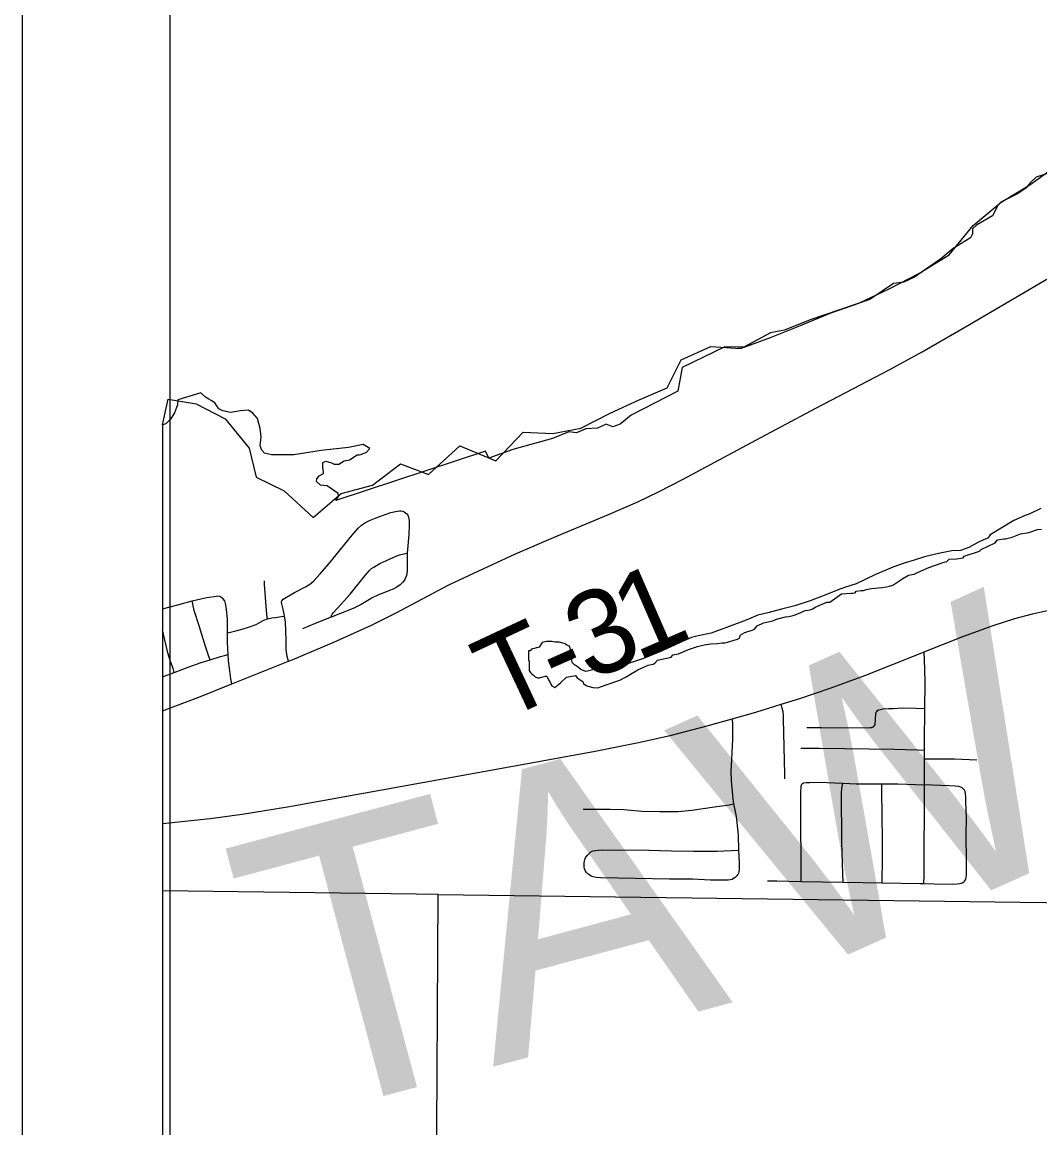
# Model space of a CAD drawing. Extents: x 63.4 to 97.4, y 0.4 to 22.4.
# Drawn here: x 65.412 to 66.101, y 16.424 to 17.173 of the extents above; entities that cross this region are included whole.
import ezdxf

# ---------------------------------------------------------------- set-up
doc = ezdxf.new("R2010")
doc.units = 0
for name, color, linetype in [('GM_X_Corporation_Text', 7, 'Continuous'), ('GM_X_County_Road', 7, 'Continuous'), ('GM_X_County_Text', 7, 'Continuous'), ('GM_X_Major_Lake', 7, 'Continuous'), ('GM_X_Minor_River', 7, 'Continuous'), ('GM_X_Section', 7, 'Continuous'), ('GM_X_State_Route', 7, 'Continuous'), ('GM_X_Township_Road', 7, 'Continuous'), ('GM_X_Township_Road_Text', 7, 'Continuous'), ('SH_Cut_Line', 7, 'Continuous'), ('SH_Data', 7, 'Continuous')]:
    doc.layers.add(name, color=color, linetype=linetype)

msp = doc.modelspace()

# ---------------------------------------------------------------- linework, layer by layer
at = {"layer": 'GM_X_Corporation_Text'}
msp.add_lwpolyline([(65.50725, 16.58499), (65.50725, 15.58676), (65.68816, 15.5852), (65.69377, 16.5825), (65.67899, 16.58257)], close=True, dxfattribs=at)
at = {"layer": 'GM_X_County_Road'}
msp.add_lwpolyline([(66.11345, 17.07252), (66.09849, 17.06781), (66.09476, 17.06423), (66.09167, 17.06049), (66.08598, 17.05659), (66.0746, 17.05107), (66.07265, 17.04863), (66.06892, 17.04164), (66.05819, 17.03546), (66.05542, 17.03286), (66.05542, 17.02945), (66.05412, 17.02685), (66.04242, 17.01969), (66.03413, 17.01254), (66.01614, 17.00026), (66.0091, 16.99694), (66.00211, 16.99596), (65.98608, 16.98501), (65.94571, 16.97126), (65.92815, 16.96427), (65.91873, 16.96248), (65.90068, 16.95273), (65.89646, 16.95273), (65.88784, 16.95305), (65.85907, 16.93908), (65.85599, 16.92315), (65.82445, 16.90689), (65.81697, 16.90071), (65.8121, 16.89893), (65.80754, 16.90071), (65.80169, 16.89811), (65.79389, 16.89763), (65.78755, 16.89486), (65.78235, 16.89551), (65.7713, 16.89096), (65.74431, 16.88348), (65.72823, 16.8778), (65.72595, 16.88251), (65.62468, 16.84903), (65.62647, 16.85179), (65.62615, 16.8539), (65.61883, 16.85894), (65.61428, 16.85943), (65.61152, 16.86187), (65.61168, 16.86382), (65.6133, 16.86577), (65.61623, 16.86723), (65.61623, 16.8687), (65.61575, 16.87113), (65.61591, 16.87487), (65.61786, 16.87569), (65.62159, 16.87454), (65.62338, 16.87357), (65.62663, 16.87357), (65.63021, 16.87585), (65.63395, 16.87649), (65.63915, 16.87991), (65.64061, 16.87991), (65.64517, 16.88153), (65.64763, 16.88434), (65.64305, 16.88706), (65.63324, 16.88498), (65.61461, 16.88284), (65.59608, 16.88007), (65.58112, 16.87991), (65.57641, 16.88105), (65.57462, 16.88316), (65.57332, 16.88609), (65.57413, 16.8921), (65.57348, 16.89779), (65.57153, 16.90462), (65.56845, 16.90819), (65.56552, 16.91014), (65.55999, 16.90982), (65.55333, 16.90852), (65.54813, 16.90966), (65.54552, 16.91112), (65.54276, 16.91518), (65.54032, 16.91681), (65.5387, 16.91762), (65.53642, 16.91892), (65.53333, 16.92201), (65.51773, 16.91729), (65.51757, 16.91372), (65.51546, 16.90835), (65.51269, 16.90413), (65.50976, 16.90121), (65.50725, 16.90012), (65.50725, 14.70733)], dxfattribs=at)
at = {"layer": 'GM_X_Major_Lake'}
msp.add_lwpolyline([(65.50725, 16.90027), (65.51106, 16.91762), (65.53002, 16.91459), (65.54973, 16.90433), (65.56604, 16.88458), (65.57059, 16.86483), (65.58956, 16.85572), (65.60927, 16.83748), (65.62823, 16.85382), (65.64947, 16.85952), (65.66842, 16.87396), (65.68738, 16.86675), (65.70862, 16.88612), (65.73289, 16.87587), (65.75146, 16.89524), (65.77156, 16.89449), (65.79052, 16.89791), (65.81024, 16.90817), (65.82995, 16.91729), (65.84891, 16.92527), (65.85839, 16.94426), (65.87849, 16.95338), (65.89858, 16.95186), (65.91868, 16.95946), (65.93916, 16.96744), (65.95925, 16.9758), (65.97859, 16.98264), (65.99944, 16.99252), (66.01916, 17.00278), (66.03963, 17.01532), (66.05594, 17.03507), (66.07489, 17.05103), (66.09423, 17.06281), (66.11926, 17.08066)], dxfattribs=at)
at = {"layer": 'GM_X_Minor_River'}
for points in [[(66.10181, 16.84376), (66.09419, 16.84002), (66.09114, 16.83891), (66.08352, 16.83555), (66.06749, 16.82579), (66.06595, 16.82353), (66.06291, 16.82241), (66.0591, 16.82054), (66.05299, 16.81717), (66.04728, 16.81531), (66.04158, 16.81498), (66.03245, 16.81314), (66.02294, 16.81094), (66.01609, 16.80871), (66.01, 16.80686), (66.00162, 16.80388), (65.98942, 16.79866), (65.97684, 16.79268), (65.96885, 16.79008), (65.96466, 16.78859), (65.95628, 16.78523), (65.94561, 16.78114), (65.93533, 16.7778), (65.9262, 16.77559), (65.91706, 16.773), (65.91022, 16.77153), (65.90221, 16.76817), (65.89079, 16.7637), (65.8786, 16.75923), (65.86985, 16.7574), (65.86528, 16.7563), (65.85766, 16.75293), (65.84546, 16.74733), (65.83289, 16.74211), (65.82261, 16.73877), (65.81615, 16.73768), (65.81043, 16.73582), (65.80549, 16.73472), (65.80397, 16.73511), (65.79865, 16.73439), (65.79484, 16.73366), (65.7937, 16.73329), (65.79219, 16.73406), (65.79067, 16.73445), (65.78879, 16.73598), (65.78614, 16.7379), (65.78463, 16.73943), (65.78427, 16.74133), (65.78428, 16.74285), (65.78392, 16.74513), (65.78393, 16.74741), (65.78319, 16.74894), (65.78282, 16.75046), (65.78093, 16.75123), (65.77979, 16.752), (65.776, 16.75316), (65.77296, 16.75319), (65.77069, 16.75359), (65.76727, 16.75361), (65.76423, 16.75287), (65.76231, 16.74985), (65.75698, 16.74837), (65.75621, 16.74724), (65.75507, 16.74725), (65.75505, 16.74421), (65.75502, 16.74117), (65.75539, 16.74003), (65.75535, 16.73395), (65.7561, 16.73281), (65.75723, 16.73166), (65.75836, 16.73089), (65.75949, 16.72975), (65.76101, 16.72898), (65.76252, 16.72896), (65.76633, 16.73007), (65.76747, 16.73007), (65.76859, 16.72778), (65.76934, 16.72626), (65.77009, 16.72473), (65.77084, 16.72359), (65.77273, 16.72243), (65.77693, 16.72582), (65.78076, 16.72959), (65.78685, 16.73068), (65.78798, 16.72915), (65.78986, 16.72762), (65.79175, 16.72647), (65.79213, 16.72532), (65.79363, 16.72417), (65.79515, 16.7234), (65.79856, 16.72262), (65.80198, 16.72221), (65.80693, 16.72407)], [(65.80693, 16.72407), (65.81683, 16.72742), (65.82102, 16.72967), (65.82407, 16.73154), (65.82904, 16.73454), (65.8359, 16.73753), (65.83932, 16.73826), (65.84046, 16.73901), (65.84238, 16.7409), (65.85151, 16.74311), (65.85266, 16.74462), (65.85646, 16.74535), (65.86332, 16.74834), (65.86941, 16.75019), (65.87398, 16.75129), (65.87816, 16.75202), (65.88273, 16.75237), (65.88615, 16.75272), (65.88805, 16.75271), (65.88957, 16.75308), (65.89642, 16.7553), (65.89795, 16.75605), (65.89834, 16.75795), (65.90139, 16.75982), (65.90634, 16.7613), (65.90787, 16.76205), (65.90978, 16.76432), (65.91398, 16.76618), (65.92044, 16.76765), (65.92273, 16.76878), (65.92882, 16.77025), (65.9311, 16.77061), (65.93414, 16.77135), (65.93719, 16.77247), (65.94215, 16.77471), (65.94557, 16.77506), (65.94747, 16.77581), (65.949, 16.77693), (65.957, 16.78029), (65.9589, 16.78028), (65.96692, 16.78591), (65.97338, 16.78625), (65.97452, 16.78624), (65.97604, 16.78661), (65.97681, 16.78774), (65.98023, 16.78809), (65.98175, 16.78808), (65.98365, 16.78883), (65.98708, 16.78956), (65.9943, 16.79026), (65.99734, 16.79062), (65.99924, 16.79099), (66.00152, 16.79173), (66.0084, 16.79624), (66.01221, 16.79849), (66.01601, 16.79922), (66.0183, 16.80034), (66.02592, 16.8037), (66.0343, 16.80667), (66.03544, 16.80705), (66.03811, 16.80779), (66.03964, 16.80929), (66.04458, 16.80964), (66.04914, 16.81036), (66.04991, 16.8115), (66.06019, 16.81484), (66.06134, 16.81597), (66.07087, 16.82045), (66.0724, 16.82234), (66.07659, 16.82307), (66.07773, 16.82306), (66.08229, 16.82416), (66.08801, 16.8264), (66.09371, 16.8275), (66.09942, 16.82935), (66.10209, 16.82971)]]:
    msp.add_lwpolyline(points, dxfattribs=at)
at = {"layer": 'GM_X_Section'}
msp.add_lwpolyline([(66.68776, 16.56928), (66.716, 16.56874), (66.70719, 15.57748), (66.70364, 15.57723), (65.68816, 15.5852), (65.69377, 16.5825)], close=True, dxfattribs=at)
at = {"layer": 'GM_X_State_Route'}
msp.add_lwpolyline([(65.50725, 16.63058), (65.53967, 16.63392), (65.56126, 16.63686), (65.59197, 16.64181), (65.68072, 16.65771), (65.7419, 16.66891), (65.80002, 16.67946), (65.83054, 16.68546), (65.85179, 16.69028), (65.8759, 16.69649), (65.89273, 16.7013), (65.9088, 16.70591), (65.92589, 16.71117), (65.93854, 16.71506), (65.95917, 16.72206), (65.98252, 16.73068), (66.02012, 16.74555), (66.02288, 16.74664), (66.04902, 16.75696), (66.06945, 16.76436), (66.08421, 16.76911), (66.09617, 16.77234), (66.1113, 16.77566)], dxfattribs=at)
at = {"layer": 'GM_X_Township_Road'}
for p, q in [((65.55432, 16.72498), (65.59259, 16.74035)), ((65.50725, 16.72971), (65.51532, 16.73273)), ((66.02296, 16.67425), (66.02297, 16.68014)), ((65.93953, 16.59131), (65.96786, 16.59078)), ((65.96786, 16.59078), (65.99438, 16.59031))]:
    msp.add_line(p, q, dxfattribs=at)
for points in [[(65.59259, 16.74035), (65.59502, 16.74133), (65.62337, 16.75324), (65.64882, 16.76471), (65.66548, 16.77301), (65.70117, 16.79192), (65.71801, 16.79998), (65.74624, 16.81297), (65.77193, 16.82404), (65.8092, 16.83953), (65.8291, 16.84824), (65.84308, 16.85488), (65.85959, 16.86344), (65.90882, 16.88996), (65.94996, 16.91189), (65.99959, 16.93762), (66.02131, 16.94965), (66.05337, 16.96811), (66.10431, 16.99791), (66.18101, 17.04274)], [(65.58991, 16.77076), (65.58936, 16.77337), (65.58866, 16.77646), (65.58796, 16.77913), (65.58774, 16.77994), (65.58774, 16.78064), (65.58796, 16.78123), (65.58898, 16.78219), (65.59117, 16.78369), (65.59654, 16.7867), (65.60408, 16.79057), (65.60633, 16.79201), (65.60789, 16.7932), (65.60973, 16.79472), (65.61406, 16.79937), (65.61977, 16.80627), (65.63561, 16.82566), (65.63973, 16.83031), (65.64203, 16.8324), (65.64459, 16.83414), (65.64736, 16.83555), (65.65314, 16.8378), (65.66194, 16.84089), (65.66499, 16.84172), (65.66764, 16.84215), (65.66888, 16.84212), (65.66987, 16.84186), (65.67077, 16.84146), (65.67186, 16.84074), (65.67266, 16.84008), (65.67324, 16.83921), (65.67382, 16.83784), (65.67411, 16.8366), (65.67418, 16.83544), (65.67426, 16.83217), (65.67393, 16.82612), (65.67286, 16.81332)], [(65.62146, 16.77009), (65.62171, 16.77133), (65.62207, 16.77206), (65.62279, 16.77308), (65.62585, 16.77627), (65.63426, 16.78571), (65.64341, 16.79704), (65.6458, 16.79986), (65.64733, 16.80161), (65.64878, 16.80299), (65.65023, 16.804), (65.65205, 16.80516), (65.65437, 16.8064), (65.66584, 16.81163), (65.6678, 16.81228), (65.66947, 16.81264), (65.67286, 16.81332)], [(65.67286, 16.81332), (65.67283, 16.80754), (65.67293, 16.80444), (65.67285, 16.80132), (65.67237, 16.79842), (65.67178, 16.79677), (65.67107, 16.79508), (65.66983, 16.79348), (65.66816, 16.79188), (65.66597, 16.79037), (65.66337, 16.78905), (65.66098, 16.78811), (65.65819, 16.787), (65.65537, 16.78588), (65.6527, 16.78476), (65.64972, 16.78332), (65.64186, 16.77859), (65.6363, 16.77599), (65.62774, 16.77254), (65.62146, 16.77009)], [(65.57827, 16.76895), (65.57803, 16.7719), (65.57756, 16.77757), (65.57645, 16.79217), (65.57637, 16.79477)], [(65.50725, 16.77581), (65.51778, 16.77856), (65.52749, 16.78106)], [(65.52749, 16.78106), (65.53331, 16.78255), (65.53725, 16.78334), (65.54393, 16.78422)], [(65.53949, 16.74127), (65.5387, 16.74356), (65.53665, 16.74948), (65.53214, 16.76417), (65.52885, 16.77467), (65.52793, 16.77901), (65.52749, 16.78106)], [(65.55132, 16.75962), (65.55119, 16.76893), (65.55059, 16.7752), (65.55012, 16.77849), (65.54946, 16.78124), (65.54815, 16.78282), (65.54605, 16.784), (65.54393, 16.78422)], [(65.57827, 16.76895), (65.58137, 16.76957), (65.58387, 16.76996), (65.58781, 16.77048), (65.58991, 16.77076)], [(65.59259, 16.74035), (65.59171, 16.74351), (65.59106, 16.74825), (65.59106, 16.75447), (65.59048, 16.76697), (65.58991, 16.77076)], [(65.55132, 16.75962), (65.5542, 16.76024), (65.55787, 16.76103), (65.56129, 16.76195), (65.56562, 16.76339), (65.57061, 16.76523), (65.57397, 16.76686), (65.57599, 16.76799), (65.57827, 16.76895)], [(65.62146, 16.77009), (65.61055, 16.76583), (65.60213, 16.76231)], [(65.51532, 16.73273), (65.51442, 16.73528), (65.51271, 16.74014), (65.511, 16.74605), (65.50725, 16.7616)], [(65.55184, 16.74474), (65.55141, 16.75301), (65.55132, 16.75962)], [(65.51532, 16.73273), (65.52474, 16.73625), (65.53356, 16.73946), (65.53949, 16.74127)], [(65.53949, 16.74127), (65.54665, 16.74346), (65.54921, 16.74409), (65.55184, 16.74474)], [(65.55432, 16.72498), (65.55354, 16.72846), (65.5528, 16.73382), (65.55206, 16.74051), (65.55184, 16.74474)], [(66.0233, 16.70827), (66.02354, 16.72571), (66.02325, 16.73504), (66.02288, 16.74664)], [(65.50725, 16.70678), (65.53198, 16.716), (65.55432, 16.72498)], [(65.92843, 16.66081), (65.92855, 16.66388), (65.92763, 16.70106), (65.9275, 16.70349), (65.92726, 16.70604), (65.92678, 16.70851), (65.92589, 16.71117)], [(65.94345, 16.6955), (65.95335, 16.69552), (65.98429, 16.69526), (65.9862, 16.69535), (65.98733, 16.69553), (65.98818, 16.6958), (65.98873, 16.69611), (65.98945, 16.6971), (65.98963, 16.69778), (65.98994, 16.7008), (65.99012, 16.70503), (65.99034, 16.70575), (65.9907, 16.70638), (65.99129, 16.70692), (65.99196, 16.70737), (65.99291, 16.70765), (65.99494, 16.70801), (65.99863, 16.70827), (66.00173, 16.70839), (66.00791, 16.7087), (66.01717, 16.70844), (66.0233, 16.70827)], [(66.02297, 16.68014), (66.02298, 16.68527), (66.0233, 16.70827)], [(65.89273, 16.7013), (65.89302, 16.69711), (65.89316, 16.69506), (65.89302, 16.68764), (65.89248, 16.67403), (65.89203, 16.66565), (65.8922, 16.65945), (65.89331, 16.64709), (65.89379, 16.64368)], [(65.93936, 16.68147), (65.95197, 16.68144), (66.00241, 16.68088), (66.01816, 16.68031), (66.02297, 16.68014)], [(66.02291, 16.65661), (66.02294, 16.6635), (66.02296, 16.67425)], [(66.02296, 16.67425), (66.02835, 16.67427), (66.04334, 16.67432), (66.05831, 16.67364)], [(65.93953, 16.59131), (65.93949, 16.59583), (65.9392, 16.63974), (65.93938, 16.65244), (65.93948, 16.65421), (65.93958, 16.65576), (65.93977, 16.65648), (65.94006, 16.65705), (65.94054, 16.65759), (65.94141, 16.65797), (65.94301, 16.65822), (65.94541, 16.65822), (65.95173, 16.65837), (65.96777, 16.65772)], [(65.96786, 16.59078), (65.9677, 16.59643), (65.9671, 16.61812), (65.96688, 16.65131), (65.96708, 16.65398), (65.96729, 16.65551), (65.96777, 16.65772)], [(65.96777, 16.65772), (65.9768, 16.65736), (65.99416, 16.6573)], [(65.99438, 16.59031), (65.99444, 16.59357), (65.99462, 16.60407), (65.99465, 16.61926), (65.99422, 16.65269), (65.99416, 16.6573)], [(65.99416, 16.6573), (66.00503, 16.65726), (66.02291, 16.65661)], [(66.02265, 16.58978), (66.02267, 16.59505), (66.02291, 16.65661)], [(66.02265, 16.58978), (66.02952, 16.58962), (66.04208, 16.58932), (66.0452, 16.58959), (66.04707, 16.58989), (66.04846, 16.59034), (66.04956, 16.59099), (66.05016, 16.59154), (66.05067, 16.59224), (66.05099, 16.59307), (66.05121, 16.59389), (66.05141, 16.59563), (66.05141, 16.59823), (66.05143, 16.60448), (66.05129, 16.62328), (66.05131, 16.63402), (66.05107, 16.64507), (66.05099, 16.64681), (66.05089, 16.6483), (66.05074, 16.65058), (66.05041, 16.65215), (66.04996, 16.65302), (66.04904, 16.65418), (66.04838, 16.65472), (66.04764, 16.65513), (66.04623, 16.65551), (66.04374, 16.65566), (66.0395, 16.65597), (66.02291, 16.65661)], [(65.79196, 16.64025), (65.81037, 16.64028), (65.81956, 16.63984), (65.8318, 16.6389), (65.84407, 16.63848), (65.85634, 16.63868), (65.86551, 16.63943), (65.88079, 16.64165), (65.89077, 16.64321), (65.89379, 16.64368)], [(65.89379, 16.64368), (65.89491, 16.63862), (65.89556, 16.63529), (65.8961, 16.63109), (65.89682, 16.62252), (65.89723, 16.61236)], [(65.89723, 16.61236), (65.89756, 16.60392), (65.89761, 16.60075), (65.89756, 16.59907), (65.89732, 16.59774), (65.89712, 16.59692), (65.89669, 16.59601), (65.89595, 16.59507), (65.89481, 16.59391), (65.89377, 16.59315), (65.89293, 16.59267), (65.8918, 16.59235), (65.89018, 16.59219), (65.88769, 16.59208), (65.88378, 16.59203), (65.87808, 16.59208), (65.86593, 16.59273), (65.85044, 16.59284), (65.80386, 16.59364), (65.80075, 16.59395), (65.79888, 16.59427), (65.79748, 16.59476), (65.7964, 16.59546), (65.79522, 16.59637), (65.79431, 16.59734), (65.79344, 16.59863), (65.79296, 16.59981), (65.79269, 16.60116), (65.79263, 16.60229), (65.79269, 16.60385), (65.79317, 16.606), (65.79365, 16.60724), (65.79462, 16.60874), (65.79597, 16.61025), (65.79726, 16.61133), (65.79801, 16.61176), (65.79882, 16.61203), (65.80033, 16.6123), (65.80225, 16.61248), (65.80537, 16.61268), (65.83646, 16.61231), (65.85178, 16.61194), (65.86664, 16.61171), (65.8827, 16.61172), (65.89723, 16.61236)], [(65.91675, 16.59174), (65.92301, 16.5916), (65.93953, 16.59131)], [(65.99438, 16.59031), (66.02012, 16.58983), (66.02265, 16.58978)]]:
    msp.add_lwpolyline(points, dxfattribs=at)
at = {"layer": 'SH_Cut_Line'}
msp.add_lwpolyline([(66.11345, 17.07252), (66.09849, 17.06781), (66.09476, 17.06423), (66.09167, 17.06049), (66.08598, 17.05659), (66.0746, 17.05107), (66.07265, 17.04863), (66.06892, 17.04164), (66.05819, 17.03546), (66.05542, 17.03286), (66.05542, 17.02945), (66.05412, 17.02685), (66.04242, 17.01969), (66.03413, 17.01254), (66.01614, 17.00026), (66.0091, 16.99694), (66.00211, 16.99596), (65.98608, 16.98501), (65.94571, 16.97126), (65.92815, 16.96427), (65.91873, 16.96248), (65.90068, 16.95273), (65.89646, 16.95273), (65.88784, 16.95305), (65.85907, 16.93908), (65.85599, 16.92315), (65.82445, 16.90689), (65.81697, 16.90071), (65.8121, 16.89893), (65.80754, 16.90071), (65.80169, 16.89811), (65.79389, 16.89763), (65.78755, 16.89486), (65.78235, 16.89551), (65.7713, 16.89096), (65.74431, 16.88348), (65.72823, 16.8778), (65.72595, 16.88251), (65.62468, 16.84903), (65.62647, 16.85179), (65.62615, 16.8539), (65.61883, 16.85894), (65.61428, 16.85943), (65.61152, 16.86187), (65.61168, 16.86382), (65.6133, 16.86577), (65.61623, 16.86723), (65.61623, 16.8687), (65.61575, 16.87113), (65.61591, 16.87487), (65.61786, 16.87569), (65.62159, 16.87454), (65.62338, 16.87357), (65.62663, 16.87357), (65.63021, 16.87585), (65.63395, 16.87649), (65.63915, 16.87991), (65.64061, 16.87991), (65.64517, 16.88153), (65.64763, 16.88434), (65.64305, 16.88706), (65.63324, 16.88498), (65.61461, 16.88284), (65.59608, 16.88007), (65.58112, 16.87991), (65.57641, 16.88105), (65.57462, 16.88316), (65.57332, 16.88609), (65.57413, 16.8921), (65.57348, 16.89779), (65.57153, 16.90462), (65.56845, 16.90819), (65.56552, 16.91014), (65.55999, 16.90982), (65.55333, 16.90852), (65.54813, 16.90966), (65.54552, 16.91112), (65.54276, 16.91518), (65.54032, 16.91681), (65.5387, 16.91762), (65.53642, 16.91892), (65.53333, 16.92201), (65.51773, 16.91729), (65.51757, 16.91372), (65.51546, 16.90835), (65.51269, 16.90413), (65.50976, 16.90121), (65.50725, 16.90012), (65.50725, 14.70733)], dxfattribs=at)
at = {"layer": 'SH_Data'}
for p, q in [((65.41231, 21.41967), (65.41231, 14.41967)), ((65.51231, 21.31967), (65.51231, 14.51967))]:
    msp.add_line(p, q, dxfattribs=at)

# ---------------------------------------------------------------- texts
at = {"layer": 'GM_X_County_Text'}
for s, rotation, p in [('W', 24.17409, (65.92339, 16.52025)), ('A', 15.03843, (65.73059, 16.46573)), ('T', 14.98235, (65.59354, 16.42906))]:
    msp.add_text(s, height=0.18939, rotation=rotation, dxfattribs=at).set_placement(p)
at = {"layer": 'GM_X_Township_Road_Text'}
for s, rotation, p in [('1', 23.51496, (65.82822, 16.74035)), ('3', 23.59421, (65.79616, 16.72635)), ('T', 25.09106, (65.73669, 16.69904)), ('-', 23.89353, (65.7749, 16.71693))]:
    msp.add_text(s, height=0.05682, rotation=rotation, dxfattribs=at).set_placement(p)

doc.saveas('drawing.dxf')
